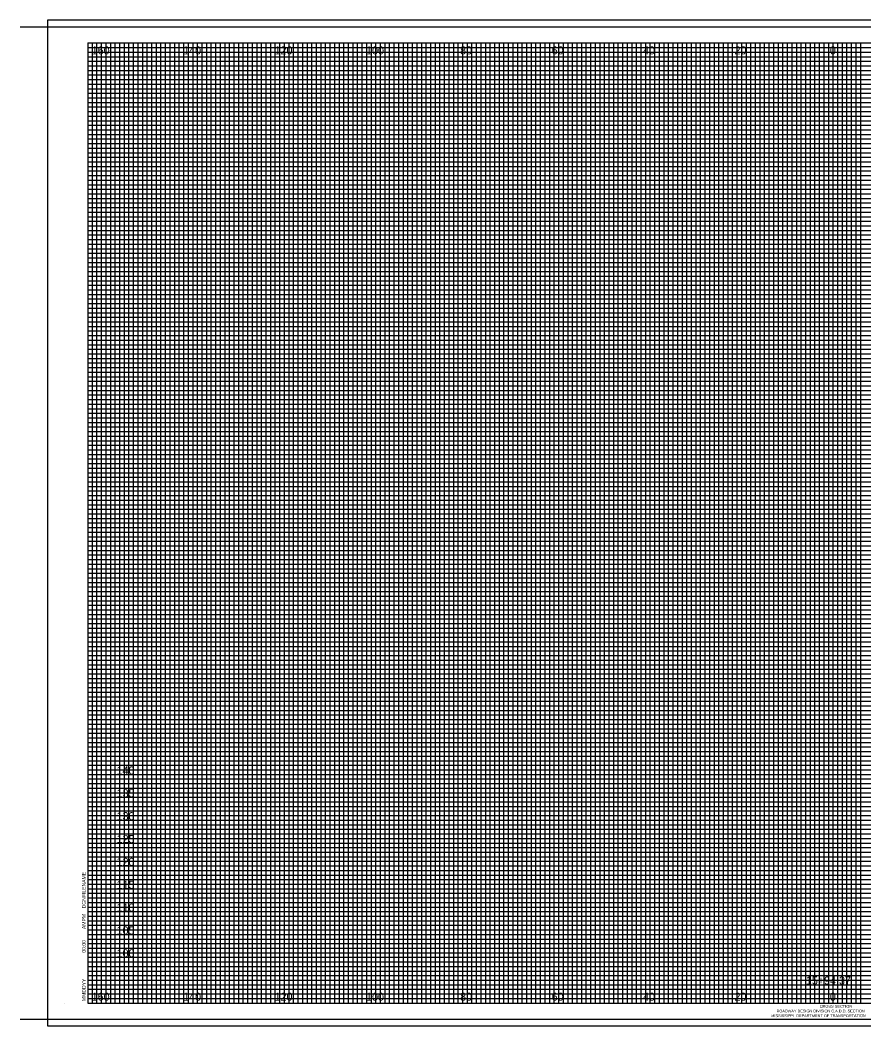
# Model space of a CAD drawing. Extents: x 21465 to 21817, y 6470 to 8070.
# Drawn here: x 21465 to 21649.5, y 7849.8 to 8069.8 of the extents above; entities that cross this region are included whole.
import ezdxf

# ---------------------------------------------------------------- set-up
doc = ezdxf.new("R2010")
doc.units = 0
for name, color, linetype in [('SHEET_BORDER', 7, 'Continuous'), ('SHEET_BORDER_TX', 7, 'Continuous'), ('SHEET_DATE_DGN_TX', 7, 'Continuous'), ('SHEET_PLOTTING_SHAPE', 7, 'Continuous'), ('XS_SHEET_LABELS_ELEVATION', 7, 'Continuous'), ('XS_SHEET_LABELS_OFFSET', 7, 'Continuous'), ('XS_SHEET_LABELS_STATION', 7, 'Continuous'), ('XS_SHEET_MAJOR_GRIDS', 7, 'Continuous'), ('XS_SHEET_MEDIUM_GRIDS', 7, 'Continuous'), ('XS_SHEET_MINOR_GRIDS', 7, 'Continuous')]:
    doc.layers.add(name, color=color, linetype=linetype)

msp = doc.modelspace()

# ---------------------------------------------------------------- linework, layer by layer
at = {"layer": 'SHEET_BORDER'}
for p, q in [((21465.04, 8068.34), (21817.04, 8068.34)), ((21479.84, 8064.84), (21814.84, 8064.84)), ((21479.84, 8064.84), (21479.84, 7854.84)), ((21623.84, 7854.84), (21623.84, 8064.84)), ((21474.84, 7854.84), (21474.84, 7854.84)), ((21479.84, 7854.84), (21814.84, 7854.84)), ((21465.04, 7851.34), (21817.04, 7851.34))]:
    msp.add_line(p, q, dxfattribs=at)
at = {"layer": 'SHEET_PLOTTING_SHAPE'}
msp.add_lwpolyline([(21471.04, 7849.84), (21817.04, 7849.84), (21817.04, 8069.84), (21471.04, 8069.84)], close=True, dxfattribs=at)
at = {"layer": 'XS_SHEET_MAJOR_GRIDS'}
for p, q in [((21484.84, 7854.84), (21484.84, 8064.84)), ((21494.84, 7854.84), (21494.84, 8064.84)), ((21504.84, 7854.84), (21504.84, 8064.84)), ((21514.84, 7854.84), (21514.84, 8064.84)), ((21524.84, 7854.84), (21524.84, 8064.84)), ((21534.84, 7854.84), (21534.84, 8064.84)), ((21544.84, 7854.84), (21544.84, 8064.84)), ((21554.84, 7854.84), (21554.84, 8064.84)), ((21564.84, 7854.84), (21564.84, 8064.84)), ((21574.84, 7854.84), (21574.84, 8064.84)), ((21584.84, 7854.84), (21584.84, 8064.84)), ((21594.84, 7854.84), (21594.84, 8064.84)), ((21604.84, 7854.84), (21604.84, 8064.84)), ((21614.84, 7854.84), (21614.84, 8064.84)), ((21624.84, 7854.84), (21624.84, 8064.84)), ((21634.84, 7854.84), (21634.84, 8064.84)), ((21644.84, 7854.84), (21644.84, 8064.84)), ((21479.84, 8054.84), (21814.84, 8054.84)), ((21479.84, 8044.84), (21814.84, 8044.84)), ((21479.84, 8034.84), (21814.84, 8034.84)), ((21479.84, 8024.84), (21814.84, 8024.84)), ((21479.84, 8014.84), (21814.84, 8014.84)), ((21479.84, 8004.84), (21814.84, 8004.84)), ((21479.84, 7994.84), (21814.84, 7994.84)), ((21479.84, 7984.84), (21814.84, 7984.84)), ((21479.84, 7974.84), (21814.84, 7974.84)), ((21479.84, 7964.84), (21814.84, 7964.84)), ((21479.84, 7954.84), (21814.84, 7954.84)), ((21479.84, 7944.84), (21814.84, 7944.84)), ((21479.84, 7934.84), (21814.84, 7934.84)), ((21479.84, 7924.84), (21814.84, 7924.84)), ((21479.84, 7914.84), (21814.84, 7914.84)), ((21479.84, 7904.84), (21814.84, 7904.84)), ((21479.84, 7894.84), (21814.84, 7894.84)), ((21479.84, 7884.84), (21814.84, 7884.84)), ((21479.84, 7874.84), (21814.84, 7874.84)), ((21479.84, 7864.84), (21814.84, 7864.84))]:
    msp.add_line(p, q, dxfattribs=at)
at = {"layer": 'XS_SHEET_MEDIUM_GRIDS'}
for p, q in [((21489.84, 7854.84), (21489.84, 8064.84)), ((21499.84, 7854.84), (21499.84, 8064.84)), ((21509.84, 7854.84), (21509.84, 8064.84)), ((21519.84, 7854.84), (21519.84, 8064.84)), ((21529.84, 7854.84), (21529.84, 8064.84)), ((21539.84, 7854.84), (21539.84, 8064.84)), ((21549.84, 7854.84), (21549.84, 8064.84)), ((21559.84, 7854.84), (21559.84, 8064.84)), ((21569.84, 7854.84), (21569.84, 8064.84)), ((21579.84, 7854.84), (21579.84, 8064.84)), ((21589.84, 7854.84), (21589.84, 8064.84)), ((21599.84, 7854.84), (21599.84, 8064.84)), ((21609.84, 7854.84), (21609.84, 8064.84)), ((21619.84, 7854.84), (21619.84, 8064.84)), ((21629.84, 7854.84), (21629.84, 8064.84)), ((21639.84, 7854.84), (21639.84, 8064.84)), ((21479.84, 8059.84), (21787.84, 8059.84)), ((21479.84, 8049.84), (21814.84, 8049.84)), ((21479.84, 8039.84), (21814.84, 8039.84)), ((21479.84, 8029.84), (21814.84, 8029.84)), ((21479.84, 8019.84), (21814.84, 8019.84)), ((21479.84, 8009.84), (21814.84, 8009.84)), ((21479.84, 7999.84), (21814.84, 7999.84)), ((21479.84, 7989.84), (21814.84, 7989.84)), ((21479.84, 7979.84), (21814.84, 7979.84)), ((21479.84, 7969.84), (21814.84, 7969.84)), ((21479.84, 7959.84), (21814.84, 7959.84)), ((21479.84, 7949.84), (21814.84, 7949.84)), ((21479.84, 7939.84), (21814.84, 7939.84)), ((21479.84, 7929.84), (21814.84, 7929.84)), ((21479.84, 7919.84), (21814.84, 7919.84)), ((21479.84, 7909.84), (21814.84, 7909.84)), ((21479.84, 7899.84), (21814.84, 7899.84)), ((21479.84, 7889.84), (21814.84, 7889.84)), ((21479.84, 7879.84), (21814.84, 7879.84)), ((21479.84, 7869.84), (21814.84, 7869.84)), ((21479.84, 7859.84), (21804.84, 7859.84))]:
    msp.add_line(p, q, dxfattribs=at)
at = {"layer": 'XS_SHEET_MINOR_GRIDS'}
for p, q in [((21479.84, 8063.84), (21787.84, 8063.84)), ((21480.84, 7854.84), (21480.84, 8064.84)), ((21481.84, 7854.84), (21481.84, 8064.84)), ((21482.84, 7854.84), (21482.84, 8064.84)), ((21483.84, 7854.84), (21483.84, 8064.84)), ((21485.84, 7854.84), (21485.84, 8064.84)), ((21486.84, 7854.84), (21486.84, 8064.84)), ((21487.84, 7854.84), (21487.84, 8064.84)), ((21488.84, 7854.84), (21488.84, 8064.84)), ((21490.84, 7854.84), (21490.84, 8064.84)), ((21491.84, 7854.84), (21491.84, 8064.84)), ((21492.84, 7854.84), (21492.84, 8064.84)), ((21493.84, 7854.84), (21493.84, 8064.84)), ((21495.84, 7854.84), (21495.84, 8064.84)), ((21496.84, 7854.84), (21496.84, 8064.84)), ((21497.84, 7854.84), (21497.84, 8064.84)), ((21498.84, 7854.84), (21498.84, 8064.84)), ((21500.84, 7854.84), (21500.84, 8064.84)), ((21501.84, 7854.84), (21501.84, 8064.84)), ((21502.84, 7854.84), (21502.84, 8064.84)), ((21503.84, 7854.84), (21503.84, 8064.84)), ((21505.84, 7854.84), (21505.84, 8064.84)), ((21506.84, 7854.84), (21506.84, 8064.84)), ((21507.84, 7854.84), (21507.84, 8064.84)), ((21508.84, 7854.84), (21508.84, 8064.84)), ((21510.84, 7854.84), (21510.84, 8064.84)), ((21511.84, 7854.84), (21511.84, 8064.84)), ((21512.84, 7854.84), (21512.84, 8064.84)), ((21513.84, 7854.84), (21513.84, 8064.84)), ((21515.84, 7854.84), (21515.84, 8064.84)), ((21516.84, 7854.84), (21516.84, 8064.84)), ((21517.84, 7854.84), (21517.84, 8064.84)), ((21518.84, 7854.84), (21518.84, 8064.84)), ((21520.84, 7854.84), (21520.84, 8064.84)), ((21521.84, 7854.84), (21521.84, 8064.84)), ((21522.84, 7854.84), (21522.84, 8064.84)), ((21523.84, 7854.84), (21523.84, 8064.84)), ((21525.84, 7854.84), (21525.84, 8064.84)), ((21526.84, 7854.84), (21526.84, 8064.84)), ((21527.84, 7854.84), (21527.84, 8064.84)), ((21528.84, 7854.84), (21528.84, 8064.84)), ((21530.84, 7854.84), (21530.84, 8064.84)), ((21531.84, 7854.84), (21531.84, 8064.84)), ((21532.84, 7854.84), (21532.84, 8064.84)), ((21533.84, 7854.84), (21533.84, 8064.84)), ((21535.84, 7854.84), (21535.84, 8064.84)), ((21536.84, 7854.84), (21536.84, 8064.84)), ((21537.84, 7854.84), (21537.84, 8064.84)), ((21538.84, 7854.84), (21538.84, 8064.84)), ((21540.84, 7854.84), (21540.84, 8064.84)), ((21541.84, 7854.84), (21541.84, 8064.84)), ((21542.84, 7854.84), (21542.84, 8064.84)), ((21543.84, 7854.84), (21543.84, 8064.84)), ((21545.84, 7854.84), (21545.84, 8064.84)), ((21546.84, 7854.84), (21546.84, 8064.84)), ((21547.84, 7854.84), (21547.84, 8064.84)), ((21548.84, 7854.84), (21548.84, 8064.84)), ((21550.84, 7854.84), (21550.84, 8064.84)), ((21551.84, 7854.84), (21551.84, 8064.84)), ((21552.84, 7854.84), (21552.84, 8064.84)), ((21553.84, 7854.84), (21553.84, 8064.84)), ((21555.84, 7854.84), (21555.84, 8064.84)), ((21556.84, 7854.84), (21556.84, 8064.84)), ((21557.84, 7854.84), (21557.84, 8064.84)), ((21558.84, 7854.84), (21558.84, 8064.84)), ((21560.84, 7854.84), (21560.84, 8064.84)), ((21561.84, 7854.84), (21561.84, 8064.84)), ((21562.84, 7854.84), (21562.84, 8064.84)), ((21563.84, 7854.84), (21563.84, 8064.84)), ((21565.84, 7854.84), (21565.84, 8064.84)), ((21566.84, 7854.84), (21566.84, 8064.84)), ((21567.84, 7854.84), (21567.84, 8064.84)), ((21568.84, 7854.84), (21568.84, 8064.84)), ((21570.84, 7854.84), (21570.84, 8064.84)), ((21571.84, 7854.84), (21571.84, 8064.84)), ((21572.84, 7854.84), (21572.84, 8064.84)), ((21573.84, 7854.84), (21573.84, 8064.84)), ((21575.84, 7854.84), (21575.84, 8064.84)), ((21576.84, 7854.84), (21576.84, 8064.84)), ((21577.84, 7854.84), (21577.84, 8064.84)), ((21578.84, 7854.84), (21578.84, 8064.84)), ((21580.84, 7854.84), (21580.84, 8064.84)), ((21581.84, 7854.84), (21581.84, 8064.84)), ((21582.84, 7854.84), (21582.84, 8064.84)), ((21583.84, 7854.84), (21583.84, 8064.84)), ((21585.84, 7854.84), (21585.84, 8064.84)), ((21586.84, 7854.84), (21586.84, 8064.84)), ((21587.84, 7854.84), (21587.84, 8064.84)), ((21588.84, 7854.84), (21588.84, 8064.84)), ((21590.84, 7854.84), (21590.84, 8064.84)), ((21591.84, 7854.84), (21591.84, 8064.84)), ((21592.84, 7854.84), (21592.84, 8064.84)), ((21593.84, 7854.84), (21593.84, 8064.84)), ((21595.84, 7854.84), (21595.84, 8064.84)), ((21596.84, 7854.84), (21596.84, 8064.84)), ((21597.84, 7854.84), (21597.84, 8064.84)), ((21598.84, 7854.84), (21598.84, 8064.84)), ((21600.84, 7854.84), (21600.84, 8064.84)), ((21601.84, 7854.84), (21601.84, 8064.84)), ((21602.84, 7854.84), (21602.84, 8064.84)), ((21603.84, 7854.84), (21603.84, 8064.84)), ((21605.84, 7854.84), (21605.84, 8064.84)), ((21606.84, 7854.84), (21606.84, 8064.84)), ((21607.84, 7854.84), (21607.84, 8064.84)), ((21608.84, 7854.84), (21608.84, 8064.84)), ((21610.84, 7854.84), (21610.84, 8064.84)), ((21611.84, 7854.84), (21611.84, 8064.84)), ((21612.84, 7854.84), (21612.84, 8064.84)), ((21613.84, 7854.84), (21613.84, 8064.84)), ((21615.84, 7854.84), (21615.84, 8064.84)), ((21616.84, 7854.84), (21616.84, 8064.84)), ((21617.84, 7854.84), (21617.84, 8064.84)), ((21618.84, 7854.84), (21618.84, 8064.84)), ((21620.84, 7854.84), (21620.84, 8064.84)), ((21621.84, 7854.84), (21621.84, 8064.84)), ((21622.84, 7854.84), (21622.84, 8064.84)), ((21625.84, 7854.84), (21625.84, 8064.84)), ((21626.84, 7854.84), (21626.84, 8064.84)), ((21627.84, 7854.84), (21627.84, 8064.84)), ((21628.84, 7854.84), (21628.84, 8064.84)), ((21630.84, 7854.84), (21630.84, 8064.84)), ((21631.84, 7854.84), (21631.84, 8064.84)), ((21632.84, 7854.84), (21632.84, 8064.84)), ((21633.84, 7854.84), (21633.84, 8064.84)), ((21635.84, 7854.84), (21635.84, 8064.84)), ((21636.84, 7854.84), (21636.84, 8064.84)), ((21637.84, 7854.84), (21637.84, 8064.84)), ((21638.84, 7854.84), (21638.84, 8064.84)), ((21640.84, 7854.84), (21640.84, 8064.84)), ((21641.84, 7854.84), (21641.84, 8064.84)), ((21642.84, 7854.84), (21642.84, 8064.84)), ((21643.84, 7854.84), (21643.84, 8064.84)), ((21645.84, 7854.84), (21645.84, 8064.84)), ((21646.84, 7854.84), (21646.84, 8064.84)), ((21647.84, 7854.84), (21647.84, 8064.84)), ((21648.84, 7854.84), (21648.84, 8064.84)), ((21479.84, 8062.84), (21787.84, 8062.84)), ((21479.84, 8061.84), (21787.84, 8061.84)), ((21479.84, 8060.84), (21787.84, 8060.84)), ((21479.84, 8058.84), (21787.84, 8058.84)), ((21479.84, 8057.84), (21787.84, 8057.84)), ((21479.84, 8056.84), (21787.84, 8056.84)), ((21479.84, 8055.84), (21814.84, 8055.84)), ((21479.84, 8053.84), (21814.84, 8053.84)), ((21479.84, 8052.84), (21814.84, 8052.84)), ((21479.84, 8051.84), (21814.84, 8051.84)), ((21479.84, 8050.84), (21814.84, 8050.84)), ((21479.84, 8048.84), (21814.84, 8048.84)), ((21479.84, 8047.84), (21814.84, 8047.84)), ((21479.84, 8046.84), (21814.84, 8046.84)), ((21479.84, 8045.84), (21814.84, 8045.84)), ((21479.84, 8043.84), (21814.84, 8043.84)), ((21479.84, 8042.84), (21814.84, 8042.84)), ((21479.84, 8041.84), (21814.84, 8041.84)), ((21479.84, 8040.84), (21814.84, 8040.84)), ((21479.84, 8038.84), (21814.84, 8038.84)), ((21479.84, 8037.84), (21814.84, 8037.84)), ((21479.84, 8036.84), (21814.84, 8036.84)), ((21479.84, 8035.84), (21814.84, 8035.84)), ((21479.84, 8033.84), (21814.84, 8033.84)), ((21479.84, 8032.84), (21814.84, 8032.84)), ((21479.84, 8031.84), (21814.84, 8031.84)), ((21479.84, 8030.84), (21814.84, 8030.84)), ((21479.84, 8028.84), (21814.84, 8028.84)), ((21479.84, 8027.84), (21814.84, 8027.84)), ((21479.84, 8026.84), (21814.84, 8026.84)), ((21479.84, 8025.84), (21814.84, 8025.84)), ((21479.84, 8023.84), (21814.84, 8023.84)), ((21479.84, 8022.84), (21814.84, 8022.84)), ((21479.84, 8021.84), (21814.84, 8021.84)), ((21479.84, 8020.84), (21814.84, 8020.84)), ((21479.84, 8018.84), (21814.84, 8018.84)), ((21479.84, 8017.84), (21814.84, 8017.84)), ((21479.84, 8016.84), (21814.84, 8016.84)), ((21479.84, 8015.84), (21814.84, 8015.84)), ((21479.84, 8013.84), (21814.84, 8013.84)), ((21479.84, 8012.84), (21814.84, 8012.84)), ((21479.84, 8011.84), (21814.84, 8011.84)), ((21479.84, 8010.84), (21814.84, 8010.84)), ((21479.84, 8008.84), (21814.84, 8008.84)), ((21479.84, 8007.84), (21814.84, 8007.84)), ((21479.84, 8006.84), (21814.84, 8006.84)), ((21479.84, 8005.84), (21814.84, 8005.84)), ((21479.84, 8003.84), (21814.84, 8003.84)), ((21479.84, 8002.84), (21814.84, 8002.84)), ((21479.84, 8001.84), (21814.84, 8001.84)), ((21479.84, 8000.84), (21814.84, 8000.84)), ((21479.84, 7998.84), (21814.84, 7998.84)), ((21479.84, 7997.84), (21814.84, 7997.84)), ((21479.84, 7996.84), (21814.84, 7996.84)), ((21479.84, 7995.84), (21814.84, 7995.84)), ((21479.84, 7993.84), (21814.84, 7993.84)), ((21479.84, 7992.84), (21814.84, 7992.84)), ((21479.84, 7991.84), (21814.84, 7991.84)), ((21479.84, 7990.84), (21814.84, 7990.84)), ((21479.84, 7988.84), (21814.84, 7988.84)), ((21479.84, 7987.84), (21814.84, 7987.84)), ((21479.84, 7986.84), (21814.84, 7986.84)), ((21479.84, 7985.84), (21814.84, 7985.84)), ((21479.84, 7983.84), (21814.84, 7983.84)), ((21479.84, 7982.84), (21814.84, 7982.84)), ((21479.84, 7981.84), (21814.84, 7981.84)), ((21479.84, 7980.84), (21814.84, 7980.84)), ((21479.84, 7978.84), (21814.84, 7978.84)), ((21479.84, 7977.84), (21814.84, 7977.84)), ((21479.84, 7976.84), (21814.84, 7976.84)), ((21479.84, 7975.84), (21814.84, 7975.84)), ((21479.84, 7973.84), (21814.84, 7973.84)), ((21479.84, 7972.84), (21814.84, 7972.84)), ((21479.84, 7971.84), (21814.84, 7971.84)), ((21479.84, 7970.84), (21814.84, 7970.84)), ((21479.84, 7968.84), (21814.84, 7968.84)), ((21479.84, 7967.84), (21814.84, 7967.84)), ((21479.84, 7966.84), (21814.84, 7966.84)), ((21479.84, 7965.84), (21814.84, 7965.84)), ((21479.84, 7963.84), (21814.84, 7963.84)), ((21479.84, 7962.84), (21814.84, 7962.84)), ((21479.84, 7961.84), (21814.84, 7961.84)), ((21479.84, 7960.84), (21814.84, 7960.84)), ((21479.84, 7958.84), (21814.84, 7958.84)), ((21479.84, 7957.84), (21814.84, 7957.84)), ((21479.84, 7956.84), (21814.84, 7956.84)), ((21479.84, 7955.84), (21814.84, 7955.84)), ((21479.84, 7953.84), (21814.84, 7953.84)), ((21479.84, 7952.84), (21814.84, 7952.84)), ((21479.84, 7951.84), (21814.84, 7951.84)), ((21479.84, 7950.84), (21814.84, 7950.84)), ((21479.84, 7948.84), (21814.84, 7948.84)), ((21479.84, 7947.84), (21814.84, 7947.84)), ((21479.84, 7946.84), (21814.84, 7946.84)), ((21479.84, 7945.84), (21814.84, 7945.84)), ((21479.84, 7943.84), (21814.84, 7943.84)), ((21479.84, 7942.84), (21814.84, 7942.84)), ((21479.84, 7941.84), (21814.84, 7941.84)), ((21479.84, 7940.84), (21814.84, 7940.84)), ((21479.84, 7938.84), (21814.84, 7938.84)), ((21479.84, 7937.84), (21814.84, 7937.84)), ((21479.84, 7936.84), (21814.84, 7936.84)), ((21479.84, 7935.84), (21814.84, 7935.84)), ((21479.84, 7933.84), (21814.84, 7933.84)), ((21479.84, 7932.84), (21814.84, 7932.84)), ((21479.84, 7931.84), (21814.84, 7931.84)), ((21479.84, 7930.84), (21814.84, 7930.84)), ((21479.84, 7928.84), (21814.84, 7928.84)), ((21479.84, 7927.84), (21814.84, 7927.84)), ((21479.84, 7926.84), (21814.84, 7926.84)), ((21479.84, 7925.84), (21814.84, 7925.84)), ((21479.84, 7923.84), (21814.84, 7923.84)), ((21479.84, 7922.84), (21814.84, 7922.84)), ((21479.84, 7921.84), (21814.84, 7921.84)), ((21479.84, 7920.84), (21814.84, 7920.84)), ((21479.84, 7918.84), (21814.84, 7918.84)), ((21479.84, 7917.84), (21814.84, 7917.84)), ((21479.84, 7916.84), (21814.84, 7916.84)), ((21479.84, 7915.84), (21814.84, 7915.84)), ((21479.84, 7913.84), (21814.84, 7913.84)), ((21479.84, 7912.84), (21814.84, 7912.84)), ((21479.84, 7911.84), (21814.84, 7911.84)), ((21479.84, 7910.84), (21814.84, 7910.84)), ((21479.84, 7908.84), (21814.84, 7908.84)), ((21479.84, 7907.84), (21814.84, 7907.84)), ((21479.84, 7906.84), (21814.84, 7906.84)), ((21479.84, 7905.84), (21814.84, 7905.84)), ((21479.84, 7903.84), (21814.84, 7903.84)), ((21479.84, 7902.84), (21814.84, 7902.84)), ((21479.84, 7901.84), (21814.84, 7901.84)), ((21479.84, 7900.84), (21814.84, 7900.84)), ((21479.84, 7898.84), (21814.84, 7898.84)), ((21479.84, 7897.84), (21814.84, 7897.84)), ((21479.84, 7896.84), (21814.84, 7896.84)), ((21479.84, 7895.84), (21814.84, 7895.84)), ((21479.84, 7893.84), (21814.84, 7893.84)), ((21479.84, 7892.84), (21814.84, 7892.84)), ((21479.84, 7891.84), (21814.84, 7891.84)), ((21479.84, 7890.84), (21814.84, 7890.84)), ((21479.84, 7888.84), (21814.84, 7888.84)), ((21479.84, 7887.84), (21814.84, 7887.84)), ((21479.84, 7886.84), (21814.84, 7886.84)), ((21479.84, 7885.84), (21814.84, 7885.84)), ((21479.84, 7883.84), (21814.84, 7883.84)), ((21479.84, 7882.84), (21814.84, 7882.84)), ((21479.84, 7881.84), (21814.84, 7881.84)), ((21479.84, 7880.84), (21814.84, 7880.84)), ((21479.84, 7878.84), (21814.84, 7878.84)), ((21479.84, 7877.84), (21814.84, 7877.84)), ((21479.84, 7876.84), (21814.84, 7876.84)), ((21479.84, 7875.84), (21814.84, 7875.84)), ((21479.84, 7875.84), (21814.84, 7875.84)), ((21479.84, 7875.84), (21814.84, 7875.84)), ((21479.84, 7873.84), (21814.84, 7873.84)), ((21479.84, 7872.84), (21814.84, 7872.84)), ((21479.84, 7871.84), (21814.84, 7871.84)), ((21479.84, 7870.84), (21814.84, 7870.84)), ((21479.84, 7868.84), (21814.84, 7868.84)), ((21479.84, 7867.84), (21814.84, 7867.84)), ((21479.84, 7866.84), (21814.84, 7866.84)), ((21479.84, 7865.84), (21814.84, 7865.84)), ((21479.84, 7863.84), (21804.84, 7863.84)), ((21479.84, 7862.84), (21804.84, 7862.84)), ((21479.84, 7861.84), (21804.84, 7861.84)), ((21479.84, 7860.84), (21804.84, 7860.84)), ((21479.84, 7860.84), (21804.84, 7860.84)), ((21479.84, 7860.84), (21804.84, 7860.84)), ((21479.84, 7858.84), (21804.84, 7858.84)), ((21479.84, 7857.84), (21804.84, 7857.84)), ((21479.84, 7856.84), (21804.84, 7856.84)), ((21479.84, 7855.84), (21804.84, 7855.84))]:
    msp.add_line(p, q, dxfattribs=at)

# ---------------------------------------------------------------- texts
at = {"layer": 'SHEET_BORDER_TX'}
for s, height, p in [('CROSS SECTION', 0.62, (21639.87, 7853.81)), ('MISSISSIPPI  DEPARTMENT OF TRANSPORTATION', 0.61, (21629.27, 7851.75)), ('ROADWAY DESIGN DIVISION C.A.D.D. SECTION', 0.61, (21630.44, 7852.78))]:
    msp.add_text(s, height=height, dxfattribs=at).set_placement(p)
at = {"layer": 'SHEET_DATE_DGN_TX'}
for s, p in [('DGNFILENAME', (21479.37, 7875.54)), ('AMPM', (21479.37, 7871.02)), ('00:00', (21479.37, 7865.84)), ('MMDDYY', (21479.37, 7855.26))]:
    msp.add_text(s, height=0.8, rotation=90, dxfattribs=at).set_placement(p)
at = {"layer": 'XS_SHEET_LABELS_ELEVATION'}
for s, p in [('  140  ', (21484.84, 7904.84)), ('  135  ', (21484.84, 7899.84)), ('  130  ', (21484.84, 7894.84)), ('  125  ', (21484.84, 7889.84)), ('  120  ', (21484.84, 7884.84)), ('  115  ', (21484.84, 7879.84)), ('  110  ', (21484.84, 7874.84)), ('  105  ', (21484.84, 7869.84)), ('  100  ', (21484.84, 7864.84))]:
    msp.add_text(s, height=1.75, dxfattribs=at).set_placement(p)
at = {"layer": 'XS_SHEET_LABELS_OFFSET'}
for s, p in [('  160  ', (21479.4, 8062.34)), ('  140  ', (21499.39, 8062.34)), ('  120  ', (21519.39, 8062.34)), ('  100  ', (21539.39, 8062.34)), ('  80  ', (21559.95, 8062.34)), ('  60  ', (21579.97, 8062.34)), ('  40  ', (21599.95, 8062.34)), ('  20  ', (21619.95, 8062.34)), ('  0  ', (21640.81, 8062.34)), ('  0  ', (21640.81, 8062.34)), ('  160  ', (21479.4, 7855.34)), ('  140  ', (21499.39, 7855.34)), ('  120  ', (21519.39, 7855.34)), ('  100  ', (21539.39, 7855.34)), ('  80  ', (21559.95, 7855.34)), ('  60  ', (21579.97, 7855.34)), ('  40  ', (21599.95, 7855.34)), ('  20  ', (21619.95, 7855.34)), ('  0  ', (21640.81, 7855.34)), ('  0  ', (21640.81, 7855.34))]:
    msp.add_text(s, height=1.75, dxfattribs=at).set_placement(p)
at = {"layer": 'XS_SHEET_LABELS_STATION'}
msp.add_text('  15+94.37  ', height=1.75, dxfattribs=at).set_placement((21635.57, 7858.89))

doc.saveas('drawing.dxf')
